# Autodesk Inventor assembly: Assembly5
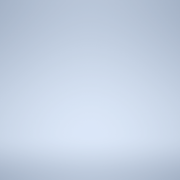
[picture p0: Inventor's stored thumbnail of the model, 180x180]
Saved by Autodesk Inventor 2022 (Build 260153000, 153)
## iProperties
Created: 2024-12
Part Number: Assembly5
Document SubType Name: Assembly
Designer: jsat7
Author: jsat7
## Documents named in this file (1)
- C:\Users\jsat7\OneDrive\デスクトップ\CAD 長田\Assembly5.iam
